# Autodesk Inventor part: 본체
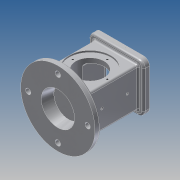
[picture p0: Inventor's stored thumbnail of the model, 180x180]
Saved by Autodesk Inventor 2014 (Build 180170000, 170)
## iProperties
Created: 2018-10
Part Number: 본체
Material: 알루미늄 6061
Document SubType Name: Modeling
Designer: kb542
Density: 2.71 g/cm^3
Appearance: 알루미늄 - 평지
Mass: 985.731 g
Surface Area: 750.08 cm^2
Volume: 363.738 cm^3
Author: kb542
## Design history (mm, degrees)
sketch "스케치1"
  geometry: C1 r 62.5 at (0, 0); 1 further point
  constraints: 1 centre point, 1 coincident
  dimensions: "d0" = 125 diameter of C1
extrude "돌출1" new body sketch "스케치1" distance "d1" = 10; taper "d2" = 0 deg
sketch "스케치2"
  geometry: L1 (-37, 33)-(37, 33); L2 (37, 33)-(37, -33); L3 (37, -33)-(-37, -33); L4 (-37, -33)-(-37, 33); C1 r 62.5 at (0, 0) reference
  constraints: 8 end point, 2 parallel, 1 horizontal, 1 perpendicular
  dimensions: "d3" = 74 distance of L1.start L1.end; "d4" = 37 distance from line of L2 C1.centre; "d5" = 66 distance between parallel lines of L3 L1; "d6" = 33 distance from line of C1.centre L3
extrude "돌출2" join sketch "스케치2" distance "d7" = 88; taper "d8" = 0 deg
sketch "스케치3"
  geometry: L1 (-46, 41)-(46, 41); L2 (46, 41)-(46, -41); L3 (46, -41)-(-46, -41); L4 (-46, -41)-(-46, 41); 1 further point
  constraints: 8 end point, 2 parallel, 1 horizontal, 1 perpendicular
  dimensions: "d9" = 92 distance of L1.start L1.end; "d10" = 46 distance from line of point (0, 0) L2; "d11" = 82 distance of L1.end L2.end; "d12" = 41 distance from line of L3 point (0, 0)
extrude "돌출3" join sketch "스케치3" distance "d13" = 10; taper "d14" = 0 deg
sketch "스케치4"
  geometry: L1 (-62.5, 0)-(62.5, 0) reference; L2 (-28, 0)-(-24.826, 18); L3 (-24.826, 18)-(0, 18); L4 (0, 18)-(0, 0); L5 (-28, 0)-(0, 0); 1 further point
  constraints: 8 end point, 2 perpendicular, 1 midpoint, 1 parallel, 1 point on line
  dimensions: "d15" = 0 distance from line of point (0, 0) L4; "d16" = 56 diameter of L2.start L4; "d17" = 18 distance between parallel lines of L3 L1; "d18" = 80 deg angle of L1 L2
revolve "회전1" sketch "스케치4" stored, may be unused: angle "d19" = 90 deg
sketch "스케치5"
  geometry: L1 (-22, 22)-(22, 22); L2 (22, 22)-(22, -22); L3 (22, -22)-(-22, -22); L4 (-22, -22)-(-22, 22); 1 further point
  constraints: 8 end point, 2 parallel, 1 horizontal, 1 perpendicular
  dimensions: "d20" = 44 distance of L1.start L1.end; "d21" = 22 distance from line of point (0, 0) L4; "d22" = 44 distance between parallel lines of L3 L1; "d23" = 22 distance from line of L1 point (0, 0)
extrude "돌출4" cut sketch "스케치5" distance "d24" = 82; taper "d25" = 0 deg
sketch "스케치6"
  geometry: L1 (-22, -22)-(-22, 22) reference; L2 (-22, 22)-(22, 22) reference; L3 (22, 22)-(22, -22) reference; L4 (22, -22)-(-22, -22) reference; L5 (-26, -26)-(26, -26); L6 (26, -26)-(26, 26); L7 (26, 26)-(-26, 26); L8 (-26, 26)-(-26, -26); L9 (-26, -26)-(26, 26); L10 (26, -26)-(-26, 26); 1 further point
  constraints: 12 end point, 2 midpoint, 2 parallel, 1 horizontal, 1 perpendicular
  dimensions: "d26" = 52 distance of L6.end L7.end; "d27" = 52 distance of L5.end L6.end
extrude "돌출5" cut sketch "스케치6" distance "d28" = 8; taper "d29" = 0 deg
sketch "스케치8"
  geometry: L1 (65, -10)-(9, -10) reference; 2 further points
  constraints: 1 vertical alignment
  dimensions: "d31" = 54 distance from line of point (37, 44) L1
hole "구멍1" sketch "스케치8" at (37, 44) diameter "d32" = 48; stored, may be unused: countersink angle "d36" = 90 deg, drill point angle "d38" = 118 deg; dims "d33" = 6, "d34" = 70, "d35" = 3, "d37" = 8
sketch "스케치9"
  geometry: C1 r 35 at (0, 0) reference; 2 further points
  constraints: 1 vertical alignment
  dimensions: "d39" = 29 distance of point (0, 29) C1.centre
sketch "스케치10"
  geometry: C1 r 62.5 at (0, 0) reference; 1 further point
  constraints: 1 horizontal alignment
  dimensions: "d40" = 50 distance of C1.centre point (-50, 0)
hole "구멍2" sketch "스케치10" at (-50, 0) diameter "d41" = 9; stored, may be unused: countersink angle "d45" = 82 deg, drill point angle "d47" = 118 deg; dims "d42" = 8.608, "d43" = 19.05, "d44" = 4.775, "d46" = 6
fillet "모깎기1" dims "d51" = 3
fillet "모깎기2" dims "d52" = 3
fillet "모깎기3" dims "d53" = 3
fillet "모깎기4" dims "d54" = 10
fillet "모깎기5" dims "d55" = 3
hole "구멍3" sketch "스케치9" diameter "d56" = 3.242; stored, may be unused: countersink angle "d60" = 82 deg, drill point angle "d62" = 118 deg; dims "d57" = 4, "d58" = 19.05, "d59" = 4.775, "d61" = 6
sketch "스케치11"
  geometry: A1 r 10 centre (-36, -31) between (-46, -31) and (-36, -41) reference; 2 further points
  constraints: 1 coincident
hole "구멍4" sketch "스케치11" at (-36, -31) diameter "d66" = 3.242; stored, may be unused: countersink angle "d70" = 82 deg, drill point angle "d72" = 118 deg; dims "d67" = 4, "d68" = 19.05, "d69" = 4.775, "d71" = 6
sketch "스케치12"
  geometry: L1 (-32.5, -13)-(92.5, -13) reference; 2 further points
  constraints: 1 vertical alignment
  dimensions: "d79" = 37 distance from line of point (30, 24) L1
hole "구멍5" sketch "스케치12" at (30, 24) diameter "d80" = 4.134; stored, may be unused: countersink angle "d84" = 82 deg, drill point angle "d86" = 118 deg; dims "d81" = 4, "d82" = 19.05, "d83" = 4.775, "d85" = 20
sketch "스케치13"
  geometry: L1 (0, 0)-(72, 0) reference; L2 (-10, 0)-(-10, -7) reference; 2 further points
  constraints: 1 other
  dimensions: "d90" = 46 distance from line of point (36, -4) L2; "d91" = 4 distance from line of L1 point (36, -4)
feature "엠보싱1" sketch "스케치13" dims "d92" = 0.5, "d93" = 0
chamfer "모따기1" distance "d94" = 1; stored, may be unused: second distance "d95" = 2, angle "d96" = 45 deg
fillet "모깎기6" dims "d97" = 3
fillet "모깎기7" dims "d98" = 3
node "솔리드1"
mirror "대칭1"
pattern_circular "원형 패턴1" dims angle "d49" = 360 deg
pattern_circular "원형 패턴2" dims angle "d64" = 360 deg
mirror "대칭2"
pattern_linear "직사각형 패턴1" dims "d75" = 72, "d78" = 62
pattern_linear "직사각형 패턴2" dims "d89" = 43
